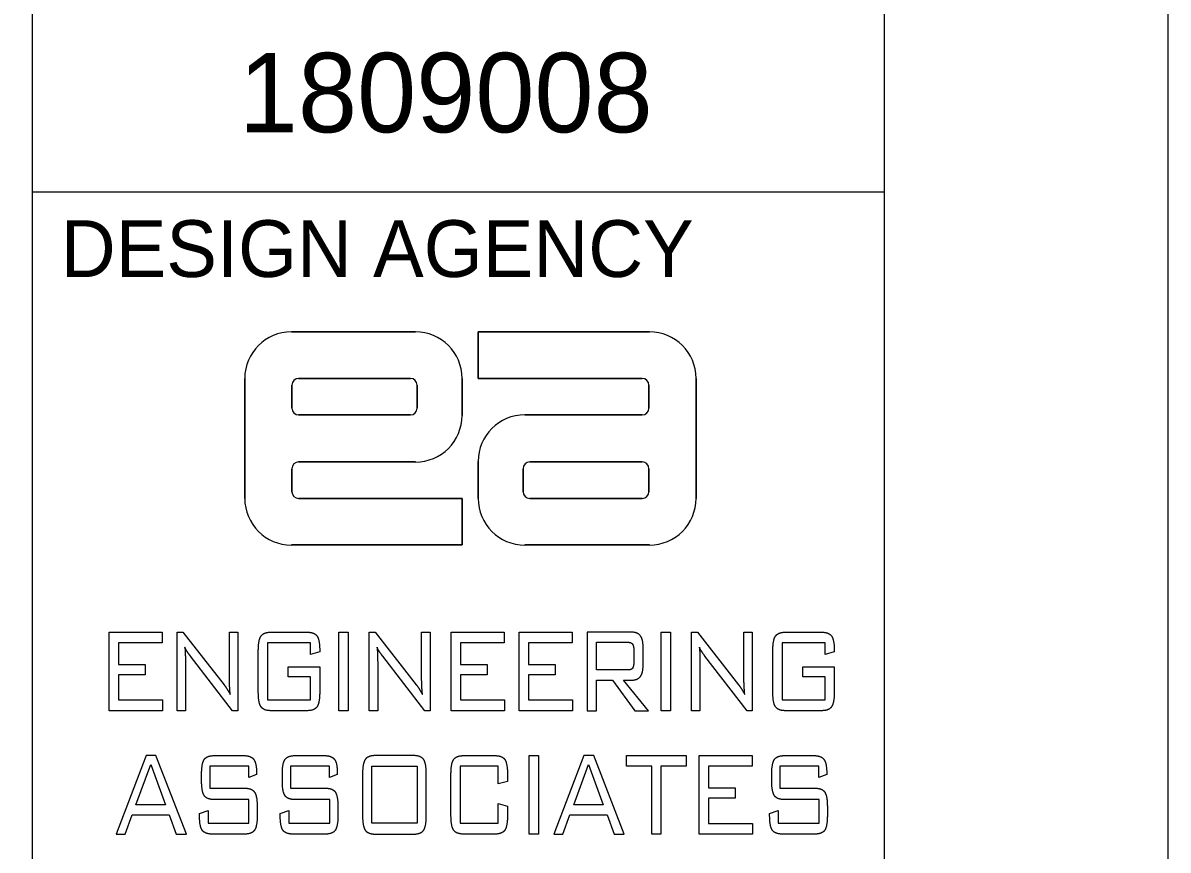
# Model space of a CAD drawing. Extents: x 0 to 34, y 0 to 22.
# Drawn here: x 31.983 to 34, y 3.84 to 5.298 of the extents above; entities that cross this region are included whole.
import ezdxf

# ---------------------------------------------------------------- set-up
doc = ezdxf.new("R2010")
doc.units = 0
for name, color, linetype in [('SH_Border', 7, 'Continuous'), ('SH_Cut_Line', 7, 'Continuous'), ('SH_Data', 7, 'Continuous'), ('TX_X_20', 7, 'Continuous')]:
    doc.layers.add(name, color=color, linetype=linetype)

msp = doc.modelspace()

# ---------------------------------------------------------------- linework, layer by layer
at = {"layer": 'SH_Border'}
for p, q in [((32, 0.5), (32, 21.5)), ((32, 5), (33.5, 5))]:
    msp.add_line(p, q, dxfattribs=at)
msp.add_lwpolyline([(1.5, 21.5), (33.5, 21.5), (33.5, 0.5), (1.5, 0.5)], close=True, dxfattribs=at)
at = {"layer": 'SH_Cut_Line'}
msp.add_lwpolyline([(0, 0), (34, 0), (34, 22), (0, 22)], close=True, dxfattribs=at)
at = {"layer": 'SH_Data'}
msp.add_line((32.75, 4), (32.75, 4), dxfattribs=at)
at = {"layer": 'TX_X_20'}
for p, q in [((32.6745, 4.7533), (32.456, 4.7533)), ((32.456, 4.7533), (32.6745, 4.7533)), ((32.785, 4.7533), (33.0865, 4.7533)), ((32.785, 4.6713), (32.785, 4.7533)), ((32.3739, 4.6713), (32.3739, 4.4597)), ((32.3739, 4.4597), (32.3739, 4.6713)), ((32.457, 4.6189), (32.457, 4.6594)), ((32.457, 4.6594), (32.457, 4.6189)), ((32.4688, 4.6713), (32.6656, 4.6713)), ((32.6656, 4.6713), (32.4688, 4.6713)), ((32.6775, 4.6594), (32.6775, 4.6189)), ((32.6775, 4.6189), (32.6775, 4.6594)), ((32.7566, 4.606), (32.7566, 4.6713)), ((32.7566, 4.6713), (32.7566, 4.606)), ((33.0737, 4.6713), (32.785, 4.6713)), ((33.0855, 4.6594), (33.0855, 4.6189)), ((33.0855, 4.6189), (33.0855, 4.6594)), ((33.1686, 4.4597), (33.1686, 4.6713)), ((33.1686, 4.6713), (33.1686, 4.4597)), ((32.6656, 4.607), (32.4688, 4.607)), ((32.4688, 4.607), (32.6656, 4.607)), ((33.0737, 4.607), (32.8671, 4.607)), ((32.8671, 4.607), (33.0737, 4.607)), ((32.4688, 4.524), (32.6745, 4.524)), ((32.6745, 4.524), (32.4688, 4.524)), ((32.785, 4.525), (32.785, 4.4597)), ((32.785, 4.4597), (32.785, 4.525)), ((32.876, 4.524), (33.0737, 4.524)), ((33.0737, 4.524), (32.876, 4.524)), ((32.457, 4.4716), (32.457, 4.5121)), ((32.457, 4.5121), (32.457, 4.4716)), ((32.8641, 4.4716), (32.8641, 4.5121)), ((32.8641, 4.5121), (32.8641, 4.4716)), ((33.0855, 4.5121), (33.0855, 4.4716)), ((33.0855, 4.4716), (33.0855, 4.5121)), ((32.4688, 4.4597), (32.7566, 4.4597)), ((32.7566, 4.4597), (32.7566, 4.3777)), ((33.0737, 4.4597), (32.876, 4.4597)), ((32.876, 4.4597), (33.0737, 4.4597)), ((32.7566, 4.3777), (32.456, 4.3777)), ((32.8671, 4.3777), (33.0865, 4.3777)), ((33.0865, 4.3777), (32.8671, 4.3777)), ((32.4205, 4.224), (32.4832, 4.224)), ((33.3267, 4.224), (33.3893, 4.224)), ((33.0755, 4.1662), (33.0755, 4.1972)), ((32.3978, 4.1184), (32.3978, 4.1913)), ((33.0591, 4.1918), (33.0591, 4.1716)), ((33.3039, 4.1184), (33.3039, 4.1913)), ((32.4832, 4.0856), (32.4205, 4.0856)), ((33.3893, 4.0856), (33.3267, 4.0856)), ((32.3205, 4.0065), (32.3719, 4.0065)), ((32.4627, 4.0065), (32.5142, 4.0065)), ((32.6711, 4.0065), (32.6041, 4.0065)), ((32.7599, 4.0065), (32.814, 4.0065)), ((33.3246, 4.0065), (33.3761, 4.0065)), ((32.2979, 3.9618), (32.2979, 3.9738)), ((32.4401, 3.9618), (32.4401, 3.9738)), ((32.5814, 3.9738), (32.5814, 3.9009)), ((32.6936, 3.9009), (32.6936, 3.9738)), ((32.7371, 3.9009), (32.7371, 3.9738)), ((33.302, 3.9618), (33.302, 3.9738)), ((32.3958, 3.9164), (32.3958, 3.9009)), ((32.538, 3.9164), (32.538, 3.9009)), ((33.3999, 3.9164), (33.3999, 3.9009)), ((32.3733, 3.8681), (32.3169, 3.8681)), ((32.5155, 3.8681), (32.4591, 3.8681)), ((32.6041, 3.8681), (32.6711, 3.8681)), ((32.814, 3.8681), (32.7599, 3.8681)), ((33.3774, 3.8681), (33.321, 3.8681))]:
    msp.add_line(p, q, dxfattribs=at)
for points in [[(33.0865, 4.7533), (32.785, 4.7533), (32.785, 4.6713), (33.0737, 4.6713)], [(32.456, 4.3777), (32.7566, 4.3777), (32.7566, 4.4597), (32.4688, 4.4597)], [(32.2695, 4.1672), (32.2695, 4.0856), (32.2547, 4.0856), (32.2547, 4.224), (32.2649, 4.224), (32.3374, 4.1315)], [(32.3469, 4.1481), (32.3469, 4.224), (32.3617, 4.224), (32.3617, 4.0856), (32.3526, 4.0856), (32.2782, 4.1819)], [(32.608, 4.1672), (32.608, 4.0856), (32.5932, 4.0856), (32.5932, 4.224), (32.6034, 4.224), (32.6759, 4.1315)], [(32.6854, 4.1481), (32.6854, 4.224), (32.7002, 4.224), (32.7002, 4.0856), (32.6912, 4.0856), (32.6168, 4.1819)], [(33.055, 4.224), (32.9769, 4.224), (32.9769, 4.0856), (32.9932, 4.0856), (32.9932, 4.1395), (33.0217, 4.1395), (33.0611, 4.0856), (33.0851, 4.0856), (33.0408, 4.1395), (33.055, 4.1395)], [(33.1756, 4.1672), (33.1756, 4.0856), (33.1608, 4.0856), (33.1608, 4.224), (33.171, 4.224), (33.2435, 4.1315)], [(33.253, 4.1481), (33.253, 4.224), (33.2678, 4.224), (33.2678, 4.0856), (33.2588, 4.0856), (33.1844, 4.1819)], [(32.5059, 4.1929), (32.5059, 4.1895), (32.4898, 4.1849), (32.4898, 4.2052), (32.4139, 4.2052), (32.4139, 4.1049), (32.4898, 4.1049), (32.4898, 4.1456), (32.4506, 4.1456), (32.4506, 4.1632), (32.5059, 4.1632), (32.5059, 4.1184)], [(33.0487, 4.1574), (32.9932, 4.1574), (32.9932, 4.2062), (33.0487, 4.2062)], [(33.4121, 4.1929), (33.4121, 4.1895), (33.3959, 4.1849), (33.3959, 4.2052), (33.3201, 4.2052), (33.3201, 4.1049), (33.3959, 4.1049), (33.3959, 4.1456), (33.3567, 4.1456), (33.3567, 4.1632), (33.4121, 4.1632), (33.4121, 4.1184)], [(32.3947, 3.9762), (32.3947, 3.9733), (32.3808, 3.9676), (32.3808, 3.9877), (32.3124, 3.9877), (32.3124, 3.9491), (32.3733, 3.9491)], [(32.5369, 3.9762), (32.5369, 3.9733), (32.523, 3.9676), (32.523, 3.9877), (32.4546, 3.9877), (32.4546, 3.9491), (32.5155, 3.9491)], [(32.8366, 3.9738), (32.8366, 3.9608), (32.8204, 3.9565), (32.8204, 3.9877), (32.7533, 3.9877), (32.7533, 3.8874), (32.8204, 3.8874), (32.8204, 3.9221), (32.8366, 3.9172), (32.8366, 3.9009)], [(33.3988, 3.9762), (33.3988, 3.9733), (33.3849, 3.9676), (33.3849, 3.9877), (33.3165, 3.9877), (33.3165, 3.9491), (33.3774, 3.9491)], [(32.2942, 3.9009), (32.2942, 3.9047), (32.3092, 3.9096), (32.3092, 3.8874), (32.3813, 3.8874), (32.3813, 3.929), (32.3205, 3.929)], [(32.4364, 3.9009), (32.4364, 3.9047), (32.4514, 3.9096), (32.4514, 3.8874), (32.5235, 3.8874), (32.5235, 3.929), (32.4627, 3.929)], [(33.2983, 3.9009), (33.2983, 3.9047), (33.3133, 3.9096), (33.3133, 3.8874), (33.3854, 3.8874), (33.3854, 3.929), (33.3246, 3.929)]]:
    msp.add_lwpolyline(points, dxfattribs=at)
for points in [[(32.1351, 4.0856), (32.1351, 4.224), (32.2283, 4.224), (32.2283, 4.2055), (32.1513, 4.2055), (32.1513, 4.167), (32.1984, 4.167), (32.1984, 4.1487), (32.1513, 4.1487), (32.1513, 4.1046), (32.2291, 4.1046), (32.2291, 4.0856)], [(32.5396, 4.0856), (32.5396, 4.224), (32.5558, 4.224), (32.5558, 4.0856)], [(32.7376, 4.0856), (32.7376, 4.224), (32.8309, 4.224), (32.8309, 4.2055), (32.7539, 4.2055), (32.7539, 4.167), (32.801, 4.167), (32.801, 4.1487), (32.7539, 4.1487), (32.7539, 4.1046), (32.8316, 4.1046), (32.8316, 4.0856)], [(32.8573, 4.0856), (32.8573, 4.224), (32.9505, 4.224), (32.9505, 4.2055), (32.8735, 4.2055), (32.8735, 4.167), (32.9206, 4.167), (32.9206, 4.1487), (32.8735, 4.1487), (32.8735, 4.1046), (32.9513, 4.1046), (32.9513, 4.0856)], [(33.1072, 4.0856), (33.1072, 4.224), (33.1234, 4.224), (33.1234, 4.0856)], [(32.1472, 3.8681), (32.1631, 3.8681), (32.1755, 3.9023), (32.241, 3.9023), (32.2534, 3.8681), (32.2712, 3.8681), (32.2174, 4.0065), (32.2001, 4.0065)], [(32.875, 3.8681), (32.875, 4.0065), (32.8912, 4.0065), (32.8912, 3.8681)], [(32.9182, 3.8681), (32.9341, 3.8681), (32.9465, 3.9023), (33.012, 3.9023), (33.0244, 3.8681), (33.0422, 3.8681), (32.9884, 4.0065), (32.9711, 4.0065)], [(33.1068, 3.9877), (33.1068, 3.8681), (33.0907, 3.8681), (33.0907, 3.9877), (33.0464, 3.9877), (33.0464, 4.0065), (33.1513, 4.0065), (33.1513, 3.9877)], [(33.1742, 3.8681), (33.1742, 4.0065), (33.2675, 4.0065), (33.2675, 3.988), (33.1905, 3.988), (33.1905, 3.9495), (33.2376, 3.9495), (33.2376, 3.9312), (33.1905, 3.9312), (33.1905, 3.8871), (33.2682, 3.8871), (33.2682, 3.8681)], [(32.1823, 3.9199), (32.2083, 3.9907), (32.2344, 3.9199)], [(32.5975, 3.8874), (32.5975, 3.9877), (32.6777, 3.9877), (32.6777, 3.8874)], [(32.9533, 3.9199), (32.9793, 3.9907), (33.0054, 3.9199)]]:
    msp.add_lwpolyline(points, close=True, dxfattribs=at)
for centre, radius, start, end in [((32.456, 4.6713), 0.0821, 90, 180), ((32.456, 4.6713), 0.0821, 90, 180), ((32.6745, 4.6713), 0.0821, 0, 90), ((32.6745, 4.6713), 0.0821, 0, 90), ((33.0865, 4.6713), 0.0821, 0, 90), ((33.0865, 4.6713), 0.0821, 0, 90), ((32.4688, 4.6594), 0.0119, 90, 180), ((32.4688, 4.6594), 0.0119, 90, 180), ((32.6656, 4.6594), 0.0119, 0, 90), ((32.6656, 4.6594), 0.0119, 0, 90), ((33.0737, 4.6594), 0.0119, 0, 90), ((33.0737, 4.6594), 0.0119, 0, 90), ((32.4688, 4.6189), 0.0119, 180, 270), ((32.4688, 4.6189), 0.0119, 180, 270), ((32.6656, 4.6189), 0.0119, 270, 0), ((32.6656, 4.6189), 0.0119, 270, 0), ((33.0737, 4.6189), 0.0119, 270, 0), ((33.0737, 4.6189), 0.0119, 270, 0), ((32.6745, 4.606), 0.0821, 270, 360), ((32.6745, 4.606), 0.0821, 270, 360), ((32.8671, 4.525), 0.0821, 90, 180), ((32.8671, 4.525), 0.0821, 90, 180), ((32.4688, 4.5121), 0.0119, 90, 180), ((32.4688, 4.5121), 0.0119, 90, 180), ((32.876, 4.5121), 0.0119, 90, 180), ((32.876, 4.5121), 0.0119, 90, 180), ((33.0737, 4.5121), 0.0119, 0, 90), ((33.0737, 4.5121), 0.0119, 0, 90), ((32.456, 4.4597), 0.0821, 180, 270), ((32.456, 4.4597), 0.0821, 180, 270), ((32.4688, 4.4716), 0.0119, 180, 270), ((32.4688, 4.4716), 0.0119, 180, 270), ((32.8671, 4.4597), 0.0821, 180, 270), ((32.8671, 4.4597), 0.0821, 180, 270), ((32.876, 4.4716), 0.0119, 180, 270), ((32.876, 4.4716), 0.0119, 180, 270), ((33.0737, 4.4716), 0.0119, 270, 0), ((33.0737, 4.4716), 0.0119, 270, 0), ((33.0865, 4.4597), 0.0821, 270, 360), ((33.0865, 4.4597), 0.0821, 270, 360)]:
    msp.add_arc(centre, radius, start, end, dxfattribs=at)
for points in [[(32.3978, 4.1913), (32.3978, 4.2102), (32.4025, 4.2171)], [(32.4025, 4.2171), (32.4072, 4.224), (32.4205, 4.224)], [(32.4832, 4.224), (32.4962, 4.224), (32.5011, 4.2173)], [(32.5011, 4.2173), (32.5059, 4.2105), (32.5059, 4.1929)], [(33.0707, 4.2177), (33.0659, 4.224), (33.055, 4.224)], [(33.0755, 4.1972), (33.0755, 4.2113), (33.0707, 4.2177)], [(33.3039, 4.1913), (33.3039, 4.2102), (33.3086, 4.2171)], [(33.3086, 4.2171), (33.3134, 4.224), (33.3267, 4.224)], [(33.3893, 4.224), (33.4023, 4.224), (33.4072, 4.2173)], [(33.4072, 4.2173), (33.4121, 4.2105), (33.4121, 4.1929)], [(32.2766, 4.184), (32.2711, 4.191), (32.2684, 4.1975)], [(32.2684, 4.1975), (32.269, 4.1912), (32.2692, 4.184)], [(32.6151, 4.184), (32.6096, 4.191), (32.6069, 4.1975)], [(32.6069, 4.1975), (32.6075, 4.1912), (32.6078, 4.184)], [(33.0487, 4.2062), (33.0546, 4.2062), (33.0569, 4.2029)], [(33.0569, 4.2029), (33.0591, 4.1997), (33.0591, 4.1918)], [(33.1827, 4.184), (33.1772, 4.191), (33.1746, 4.1975)], [(33.1746, 4.1975), (33.1751, 4.1912), (33.1754, 4.184)], [(32.2692, 4.184), (32.2695, 4.1769), (32.2695, 4.1672)], [(32.2782, 4.1819), (32.2777, 4.1825), (32.2766, 4.184)], [(32.6078, 4.184), (32.608, 4.1769), (32.608, 4.1672)], [(32.6168, 4.1819), (32.6162, 4.1825), (32.6151, 4.184)], [(33.1754, 4.184), (33.1756, 4.1769), (33.1756, 4.1672)], [(33.1844, 4.1819), (33.1838, 4.1825), (33.1827, 4.184)], [(33.0569, 4.1606), (33.0547, 4.1574), (33.0487, 4.1574)], [(33.0591, 4.1716), (33.0591, 4.1637), (33.0569, 4.1606)], [(33.0707, 4.1459), (33.0755, 4.1522), (33.0755, 4.1662)], [(32.3473, 4.128), (32.3469, 4.1353), (32.3469, 4.1481)], [(32.6858, 4.128), (32.6854, 4.1353), (32.6854, 4.1481)], [(33.055, 4.1395), (33.0659, 4.1395), (33.0707, 4.1459)], [(33.2534, 4.128), (33.253, 4.1353), (33.253, 4.1481)], [(32.3374, 4.1315), (32.3398, 4.1283), (32.3426, 4.1239)], [(32.3426, 4.1239), (32.3454, 4.1194), (32.3484, 4.114)], [(32.3484, 4.114), (32.3476, 4.1207), (32.3473, 4.128)], [(32.4025, 4.0926), (32.3978, 4.0995), (32.3978, 4.1184)], [(32.5059, 4.1184), (32.5059, 4.0994), (32.5012, 4.0925)], [(32.6759, 4.1315), (32.6784, 4.1283), (32.6812, 4.1239)], [(32.6812, 4.1239), (32.684, 4.1194), (32.6869, 4.114)], [(32.6869, 4.114), (32.6862, 4.1207), (32.6858, 4.128)], [(33.2435, 4.1315), (33.246, 4.1283), (33.2488, 4.1239)], [(33.2488, 4.1239), (33.2516, 4.1194), (33.2545, 4.114)], [(33.2545, 4.114), (33.2538, 4.1207), (33.2534, 4.128)], [(33.3086, 4.0926), (33.3039, 4.0995), (33.3039, 4.1184)], [(33.4121, 4.1184), (33.4121, 4.0994), (33.4073, 4.0925)], [(32.4205, 4.0856), (32.4072, 4.0856), (32.4025, 4.0926)], [(32.5012, 4.0925), (32.4964, 4.0856), (32.4832, 4.0856)], [(33.3267, 4.0856), (33.3134, 4.0856), (33.3086, 4.0926)], [(33.4073, 4.0925), (33.4025, 4.0856), (33.3893, 4.0856)], [(32.2979, 3.9738), (32.2979, 3.9928), (32.3026, 3.9997)], [(32.3026, 3.9997), (32.3072, 4.0065), (32.3205, 4.0065)], [(32.3719, 4.0065), (32.3849, 4.0065), (32.3898, 3.9998)], [(32.3898, 3.9998), (32.3947, 3.9931), (32.3947, 3.9762)], [(32.4401, 3.9738), (32.4401, 3.9928), (32.4448, 3.9997)], [(32.4448, 3.9997), (32.4495, 4.0065), (32.4627, 4.0065)], [(32.5142, 4.0065), (32.5271, 4.0065), (32.532, 3.9998)], [(32.532, 3.9998), (32.5369, 3.9931), (32.5369, 3.9762)], [(32.5861, 3.9996), (32.5814, 3.9927), (32.5814, 3.9738)], [(32.6041, 4.0065), (32.5908, 4.0065), (32.5861, 3.9996)], [(32.6889, 3.9997), (32.6842, 4.0065), (32.6711, 4.0065)], [(32.6936, 3.9738), (32.6936, 3.9928), (32.6889, 3.9997)], [(32.7371, 3.9738), (32.7371, 3.9928), (32.7419, 3.9997)], [(32.7419, 3.9997), (32.7467, 4.0065), (32.7599, 4.0065)], [(32.814, 4.0065), (32.8272, 4.0065), (32.8319, 3.9997)], [(32.8319, 3.9997), (32.8366, 3.9929), (32.8366, 3.9738)], [(33.302, 3.9738), (33.302, 3.9928), (33.3067, 3.9997)], [(33.3067, 3.9997), (33.3114, 4.0065), (33.3246, 4.0065)], [(33.3761, 4.0065), (33.389, 4.0065), (33.3939, 3.9998)], [(33.3939, 3.9998), (33.3988, 3.9931), (33.3988, 3.9762)], [(32.3026, 3.9359), (32.2979, 3.9428), (32.2979, 3.9618)], [(32.4448, 3.9359), (32.4401, 3.9428), (32.4401, 3.9618)], [(33.3067, 3.9359), (33.302, 3.9428), (33.302, 3.9618)], [(32.3205, 3.929), (32.3072, 3.929), (32.3026, 3.9359)], [(32.3733, 3.9491), (32.3863, 3.9491), (32.391, 3.9423)], [(32.391, 3.9423), (32.3958, 3.9355), (32.3958, 3.9164)], [(32.4627, 3.929), (32.4495, 3.929), (32.4448, 3.9359)], [(32.5155, 3.9491), (32.5285, 3.9491), (32.5333, 3.9423)], [(32.5333, 3.9423), (32.538, 3.9355), (32.538, 3.9164)], [(33.3246, 3.929), (33.3114, 3.929), (33.3067, 3.9359)], [(33.3774, 3.9491), (33.3904, 3.9491), (33.3952, 3.9423)], [(33.3952, 3.9423), (33.3999, 3.9355), (33.3999, 3.9164)], [(32.2989, 3.875), (32.2942, 3.8819), (32.2942, 3.9009)], [(32.3958, 3.9009), (32.3958, 3.8818), (32.3911, 3.875)], [(32.4411, 3.875), (32.4364, 3.8819), (32.4364, 3.9009)], [(32.538, 3.9009), (32.538, 3.8818), (32.5333, 3.875)], [(32.5814, 3.9009), (32.5814, 3.882), (32.5861, 3.8751)], [(32.6889, 3.875), (32.6936, 3.8818), (32.6936, 3.9009)], [(32.7419, 3.875), (32.7371, 3.8819), (32.7371, 3.9009)], [(32.8366, 3.9009), (32.8366, 3.8818), (32.8319, 3.875)], [(33.3031, 3.875), (33.2983, 3.8819), (33.2983, 3.9009)], [(33.3999, 3.9009), (33.3999, 3.8818), (33.3953, 3.875)], [(32.3169, 3.8681), (32.3037, 3.8681), (32.2989, 3.875)], [(32.3911, 3.875), (32.3865, 3.8681), (32.3733, 3.8681)], [(32.4591, 3.8681), (32.4459, 3.8681), (32.4411, 3.875)], [(32.5333, 3.875), (32.5287, 3.8681), (32.5155, 3.8681)], [(32.5861, 3.8751), (32.5908, 3.8681), (32.6041, 3.8681)], [(32.6711, 3.8681), (32.6842, 3.8681), (32.6889, 3.875)], [(32.7599, 3.8681), (32.7467, 3.8681), (32.7419, 3.875)], [(32.8319, 3.875), (32.8272, 3.8681), (32.814, 3.8681)], [(33.321, 3.8681), (33.3078, 3.8681), (33.3031, 3.875)], [(33.3953, 3.875), (33.3906, 3.8681), (33.3774, 3.8681)]]:
    msp.add_open_spline(points, degree=2, dxfattribs=at)

# ---------------------------------------------------------------- texts
at = {"layer": 'SH_Data'}
for s, height, p in [('1809008', 0.14, (32.3635, 5.105)), ('DESIGN AGENCY', 0.1, (32.05, 4.85))]:
    msp.add_text(s, height=height, dxfattribs=at).set_placement(p)

doc.saveas('drawing.dxf')
